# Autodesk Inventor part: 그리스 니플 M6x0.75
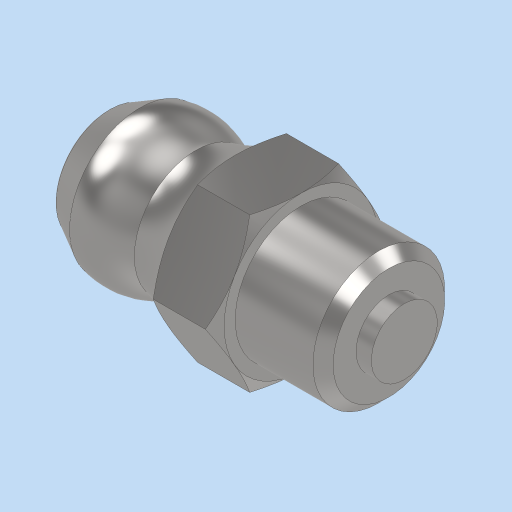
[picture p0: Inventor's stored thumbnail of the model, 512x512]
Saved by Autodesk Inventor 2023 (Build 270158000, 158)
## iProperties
Created: 2026-03
Part Number: 그리스 니플 M6x0.75
Material: 강철, 연강
Description: 윤활 니플, 원추 유형 A
Document SubType Name: Modeling
Designer: home
Density: 7.85 g/cm^3
Appearance: 기본값
Author: jhkim
Sending System: Autodesk Inventor 2026
Preprocessor: ST-DEVELOPER v20.1
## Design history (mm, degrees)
feature "Solid1"
node "솔리드1"
